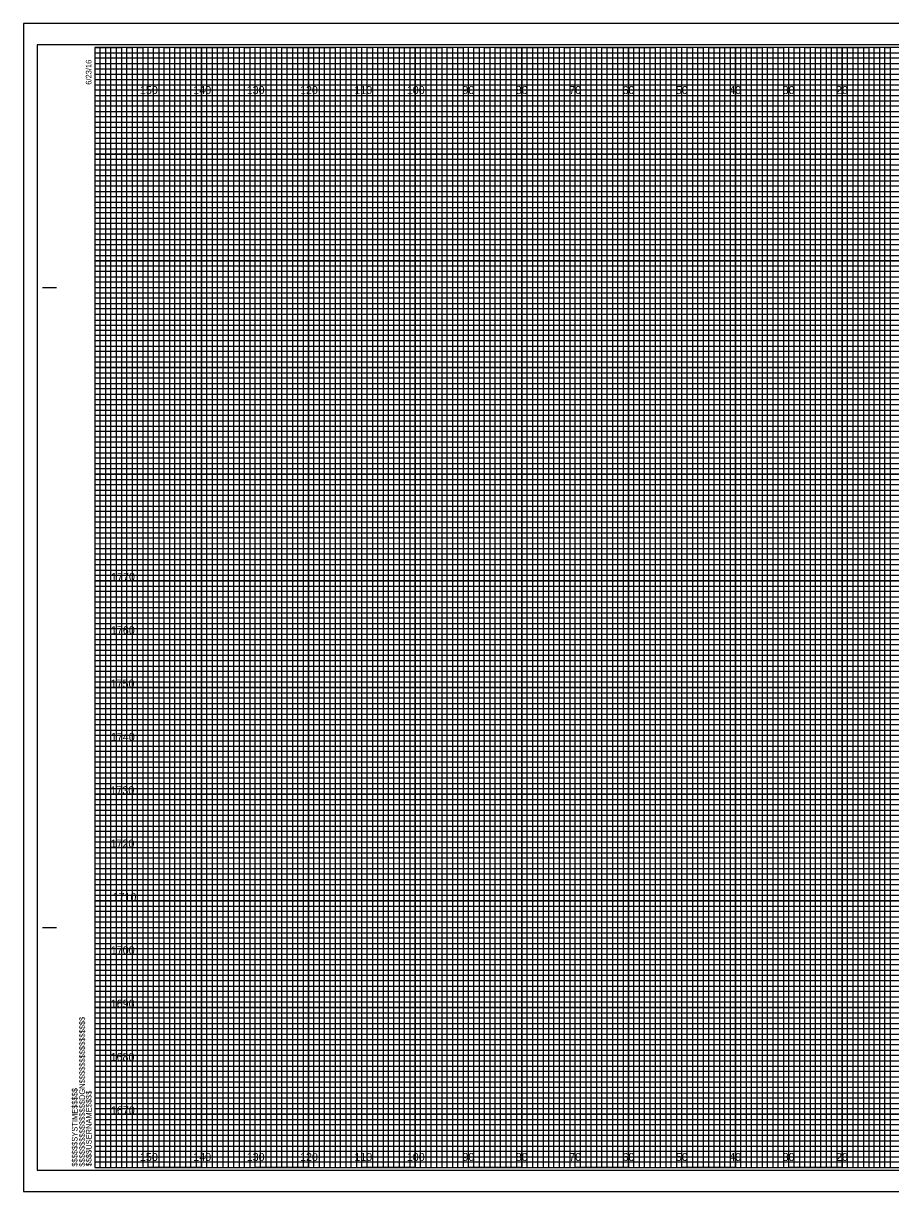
# Model space of a CAD drawing. Extents: x -419 to 4739, y -630 to 13534.
# Drawn here: x 1197.8 to 1360.3, y 199.6 to 418.6 of the extents above; entities that cross this region are included whole.
import ezdxf

# ---------------------------------------------------------------- set-up
doc = ezdxf.new("R2010")
doc.units = 0
for name, color, linetype in [('Old_Level_62', 7, 'Continuous'), ('Pattern 1', 7, 'Continuous'), ('Pattern 18', 7, 'Continuous'), ('Pattern 4', 7, 'Continuous'), ('Pattern 5', 7, 'Continuous'), ('Prop Dimension', 7, 'Continuous'), ('Prop Horizontal Alignment', 7, 'Continuous'), ('Raster_Level_0', 7, 'Continuous'), ('Scratch_Level_0', 7, 'Continuous'), ('Scratch_Level_3', 7, 'Continuous'), ('Scratch_Level_5', 7, 'Continuous')]:
    doc.layers.add(name, color=color, linetype=linetype)

msp = doc.modelspace()

# ---------------------------------------------------------------- linework, layer by layer
at = {"layer": 'Old_Level_62'}
for p, q in [((1201.42, 369.06), (1203.92, 369.06)), ((1201.52, 369.06), (1204.02, 369.06)), ((1201.42, 249.06), (1203.92, 249.06)), ((1201.52, 249.06), (1204.02, 249.06)), ((1211.22, 204.06), (1211.22, 204.06)), ((1211.22, 204.06), (1211.22, 204.06)), ((1211.22, 204.06), (1211.22, 204.06)), ((1211.22, 204.06), (1211.22, 204.06)), ((1211.22, 204.06), (1211.22, 204.06)), ((1211.22, 204.06), (1211.22, 204.06)), ((1211.22, 204.06), (1211.22, 204.06))]:
    msp.add_line(p, q, dxfattribs=at)
msp.add_lwpolyline([(1531.22, 414.06), (1211.22, 414.06), (1211.22, 204.06), (1531.22, 204.06)], close=True, dxfattribs=at)
at = {"layer": 'Pattern 18'}
msp.add_lwpolyline([(1197.82, 199.56), (1534.52, 199.56), (1534.52, 418.56), (1197.82, 418.56)], close=True, dxfattribs=at)
at = {"layer": 'Pattern 4'}
for p, q in [((1211.22, 413.06), (1471.22, 413.06)), ((1471.22, 412.04), (1211.22, 412.04)), ((1211.22, 412.04), (1211.22, 411.06)), ((1211.22, 411.06), (1471.22, 411.06)), ((1471.22, 409.95), (1211.22, 409.95)), ((1211.22, 409.95), (1211.22, 408.06)), ((1211.22, 408.06), (1531.22, 408.06))]:
    msp.add_line(p, q, dxfattribs=at)
for points in [[(1211.22, 407.06), (1481.22, 407.06), (1531.22, 407.06), (1531.22, 406.06), (1211.22, 406.06)], [(1211.22, 405.06), (1531.22, 405.06), (1531.22, 403.06), (1211.22, 403.06)], [(1211.22, 402.06), (1531.22, 402.06), (1531.22, 401.06), (1211.22, 401.04)], [(1211.22, 400.06), (1531.22, 400.06), (1531.22, 398.06), (1211.22, 398.06)], [(1211.22, 397.06), (1531.22, 397.06), (1531.22, 396.06), (1211.22, 396.06)], [(1211.22, 395.06), (1531.22, 395.06), (1531.22, 393.06), (1211.22, 393.06)], [(1211.22, 392.06), (1531.22, 392.06), (1531.22, 391.06), (1211.22, 391.06)], [(1211.22, 390.06), (1531.22, 390.06), (1531.22, 388.06), (1211.22, 388.06)], [(1211.22, 387.06), (1531.22, 387.06), (1531.22, 386.06), (1211.22, 386.06)], [(1211.22, 385.06), (1531.22, 385.06), (1531.22, 383.06), (1211.22, 383.06)], [(1211.22, 382.06), (1531.22, 382.06), (1531.22, 381.06), (1211.22, 381.06)], [(1211.22, 380.06), (1531.22, 380.06), (1531.22, 378.01), (1531.22, 377.06), (1531.22, 376.06), (1211.22, 376.06)], [(1211.22, 378.06), (1531.22, 378.06), (1531.22, 377.06), (1211.22, 377.06)], [(1211.22, 375.06), (1531.22, 375.06), (1531.22, 373.06), (1211.22, 373.09)], [(1211.22, 373.09), (1531.22, 373.06), (1531.22, 372.06), (1211.22, 372.06)], [(1211.22, 371.06), (1531.22, 371.06), (1531.22, 370.06), (1211.22, 370.06)], [(1211.22, 368.06), (1531.22, 368.06), (1531.22, 367.06), (1211.22, 367.06)], [(1211.22, 366.06), (1531.22, 366.06), (1531.22, 365.06), (1211.22, 365.06)], [(1211.15, 362.95), (1531.22, 362.95), (1531.22, 361.94), (1211.15, 361.94)], [(1211.22, 361.06), (1531.22, 361.06), (1531.22, 360.06), (1211.22, 360.06)], [(1211.22, 358.06), (1531.22, 358.06), (1531.22, 357.06), (1211.22, 357.06)], [(1211.22, 356.06), (1531.22, 356.06), (1531.22, 355.06), (1211.22, 355.06)], [(1211.22, 353.06), (1531.22, 353.06), (1531.22, 352.06), (1211.22, 352.06)], [(1211.22, 351.06), (1531.22, 351.06), (1531.22, 350.06), (1211.22, 350.06)], [(1211.22, 348.06), (1531.22, 348.06), (1531.22, 347.06), (1211.22, 347.06)], [(1211.22, 346.06), (1531.22, 346.06), (1531.22, 345.06), (1211.22, 345.06)], [(1211.22, 343.06), (1531.22, 343.06), (1531.21, 342.04), (1211.22, 342.06)], [(1211.22, 341.06), (1531.22, 341.06), (1531.22, 340.06), (1211.22, 340.06)], [(1211.22, 338.06), (1531.22, 338.06), (1531.22, 337.06), (1211.22, 337.06)], [(1211.22, 336.06), (1531.22, 336.06), (1531.22, 335.06), (1211.22, 335.06)], [(1211.22, 333.06), (1531.22, 333.06), (1531.22, 332.06), (1211.22, 332.06)], [(1211.22, 331.06), (1531.22, 331.06), (1531.22, 330.06), (1211.22, 330.06)], [(1211.22, 328.06), (1531.22, 328.06), (1531.22, 327.06), (1211.22, 327.06)], [(1211.22, 326.06), (1531.22, 326.06), (1531.22, 325.06), (1211.22, 325.06)], [(1211.22, 323.06), (1531.22, 323.06), (1531.22, 322.06), (1211.22, 322.06)], [(1211.22, 321.05), (1531.29, 320.97), (1531.22, 320.06), (1211.22, 320.06)], [(1211.22, 318.06), (1531.22, 318.06), (1531.22, 317.06), (1211.22, 317.06)], [(1211.22, 316.06), (1531.22, 316.06), (1531.22, 315.06), (1211.22, 315.06)], [(1211.22, 313.06), (1531.22, 313.06), (1531.22, 312.06), (1211.22, 312.06)], [(1211.22, 311.06), (1531.22, 311.06), (1531.22, 310.06), (1211.22, 310.06)], [(1211.22, 308.06), (1531.22, 308.06), (1531.22, 307.06), (1211.22, 307.06)], [(1211.22, 306.06), (1531.22, 306.06), (1531.22, 305.06), (1211.22, 305.06)], [(1211.22, 303.06), (1531.22, 303.06), (1531.22, 302.06), (1211.22, 302.06)], [(1211.22, 301.06), (1531.22, 301.06), (1531.22, 300.06), (1211.22, 300.06)], [(1211.22, 298.06), (1531.22, 298.06), (1531.22, 297.06), (1211.22, 297.06)], [(1211.22, 296.06), (1531.22, 296.06), (1531.22, 295.06), (1211.22, 295.06)], [(1211.22, 293.06), (1531.22, 293.06), (1531.22, 292.06), (1211.22, 292.06)], [(1211.22, 291.06), (1531.22, 291.06), (1531.22, 290.06), (1211.22, 290.06)], [(1211.22, 288.06), (1531.22, 288.06), (1531.22, 287.06), (1211.22, 287.06)], [(1211.22, 286.06), (1531.22, 286.06), (1531.22, 285.06), (1211.22, 285.06)], [(1211.22, 283.06), (1531.22, 283.06), (1531.21, 282.04), (1211.22, 282.06)], [(1211.22, 281.06), (1531.22, 281.06), (1531.22, 280.06), (1211.22, 280.06)], [(1211.22, 278.06), (1531.22, 278.06), (1531.22, 277.06), (1211.22, 277.06)], [(1211.22, 276.06), (1531.22, 276.06), (1531.22, 275.06), (1211.22, 275.06)], [(1211.22, 273.06), (1531.22, 273.06), (1531.22, 272.06), (1211.22, 272.06)], [(1211.22, 271.06), (1531.22, 271.06), (1531.22, 270.06), (1211.22, 270.06)], [(1211.22, 268.06), (1531.22, 268.06), (1531.22, 267.06), (1211.22, 267.06)], [(1211.22, 266.06), (1531.22, 266.06), (1531.22, 265.06), (1211.22, 265.06)], [(1211.22, 263.06), (1531.22, 263.06), (1531.22, 262.06), (1211.22, 262.06)], [(1211.22, 261.05), (1531.29, 260.97), (1531.22, 260.06), (1211.22, 260.06)], [(1211.22, 258.06), (1531.22, 258.06), (1531.22, 257.06), (1211.22, 257.06)], [(1211.22, 256.06), (1531.22, 256.06), (1531.22, 255.06), (1211.22, 255.06)], [(1211.22, 253.06), (1531.22, 253.06), (1531.22, 252.06), (1211.22, 252.06)], [(1211.22, 251.06), (1531.22, 251.06), (1531.22, 250.06), (1211.22, 250.06)], [(1211.22, 248.06), (1531.22, 248.06), (1531.22, 247.06), (1211.22, 247.06)], [(1211.22, 246.06), (1531.22, 246.06), (1531.22, 245.06), (1211.22, 245.06)], [(1211.22, 243.06), (1531.22, 243.06), (1531.22, 242.06), (1211.22, 242.06)], [(1211.22, 241.06), (1531.22, 241.06), (1531.22, 240.06), (1211.22, 240.06)], [(1211.22, 238.06), (1531.22, 238.06), (1531.22, 237.06), (1211.22, 237.06)], [(1211.22, 236.06), (1531.22, 236.06), (1531.22, 235.06), (1211.22, 235.06)], [(1211.22, 233.06), (1531.22, 233.06), (1531.22, 232.06), (1211.22, 232.06)], [(1211.22, 231.06), (1531.22, 231.06), (1531.22, 230.06), (1211.22, 230.06)], [(1211.22, 228.06), (1531.22, 228.06), (1531.22, 227.06), (1211.22, 227.06)], [(1211.22, 226.06), (1531.22, 226.06), (1531.22, 225.06), (1211.22, 225.06)], [(1211.22, 223.06), (1531.22, 223.06), (1531.22, 222.06), (1211.22, 222.06)], [(1211.22, 221.06), (1531.22, 221.06), (1531.22, 220.06), (1211.22, 220.06)], [(1211.22, 218.06), (1531.22, 218.06), (1531.22, 217.06), (1211.22, 217.06)], [(1211.22, 216.06), (1531.22, 216.06), (1531.22, 215.06), (1211.22, 215.06)], [(1211.22, 213.06), (1531.22, 213.06), (1531.22, 212.06), (1211.22, 212.06)], [(1211.22, 211.06), (1531.22, 211.06), (1531.22, 210.06), (1211.22, 210.06)], [(1211.22, 208.06), (1531.22, 208.06), (1531.22, 207.06), (1211.22, 207.06)], [(1211.22, 206.06), (1531.22, 206.06), (1531.22, 205.06), (1211.22, 205.06)]]:
    msp.add_lwpolyline(points, dxfattribs=at)
at = {"layer": 'Pattern 5'}
for p, q in [((1534.52, 418.56), (1197.82, 418.56)), ((1197.82, 418.56), (1197.82, 199.56)), ((1197.82, 199.56), (1534.52, 199.56))]:
    msp.add_line(p, q, dxfattribs=at)
at = {"layer": 'Prop Dimension'}
for points in [[(1211.22, 204.06), (1212.22, 204.06), (1212.22, 414.06), (1213.22, 414.06), (1213.22, 204.06)], [(1213.22, 204.06), (1214.22, 204.06), (1214.22, 414.06), (1215.22, 414.06), (1215.22, 204.06)], [(1216.22, 204.06), (1217.22, 204.06), (1217.22, 414.06), (1218.22, 414.06), (1218.22, 204.06)], [(1218.22, 204.06), (1219.22, 204.06), (1219.22, 414.06), (1220.22, 414.06), (1220.22, 204.06)], [(1221.22, 204.06), (1222.22, 204.06), (1222.22, 414.06), (1223.22, 414.06), (1223.22, 204.06)], [(1223.22, 204.06), (1224.22, 204.06), (1224.22, 414.06), (1225.22, 414.06), (1225.22, 204.06)], [(1226.22, 204.06), (1227.22, 204.06), (1227.22, 414.06), (1228.22, 414.06), (1228.22, 204.06)], [(1228.22, 204.06), (1229.22, 204.06), (1229.22, 414.06), (1230.22, 414.06), (1230.22, 204.06)], [(1231.22, 204.06), (1232.22, 204.06), (1232.22, 414.06), (1233.22, 414.06), (1233.22, 204.06)], [(1233.22, 204.06), (1234.22, 204.06), (1234.22, 414.06), (1235.22, 414.06), (1235.22, 204.06)], [(1236.22, 204.06), (1237.22, 204.06), (1237.22, 414.06), (1238.22, 414.06), (1238.22, 204.06)], [(1238.22, 204.06), (1239.22, 204.06), (1239.22, 414.06), (1240.22, 414.06), (1240.22, 204.06)], [(1241.22, 204.06), (1242.22, 204.06), (1242.22, 414.06), (1243.22, 414.06), (1243.22, 204.06)], [(1243.22, 204.06), (1244.22, 204.06), (1244.22, 414.06), (1245.22, 414.06), (1245.22, 204.06)], [(1246.22, 204.06), (1247.22, 204.06), (1247.22, 414.06), (1248.22, 414.06), (1248.22, 204.06)], [(1248.22, 204.06), (1249.22, 204.06), (1249.22, 414.06), (1250.22, 414.06), (1250.22, 204.06)], [(1251.22, 204.06), (1252.22, 204.06), (1252.22, 414.06), (1253.22, 414.06), (1253.22, 204.06)], [(1253.22, 204.06), (1254.22, 204.06), (1254.22, 414.06), (1255.22, 414.06), (1255.22, 204.06)], [(1256.22, 204.06), (1257.22, 204.06), (1257.22, 414.06), (1258.22, 414.06), (1258.22, 204.06)], [(1258.22, 204.06), (1259.22, 204.06), (1259.22, 414.06), (1260.22, 414.06), (1260.22, 204.06)], [(1261.22, 204.06), (1262.22, 204.06), (1262.22, 414.06), (1263.22, 414.06), (1263.22, 204.06)], [(1263.22, 204.06), (1264.22, 204.06), (1264.22, 414.06), (1265.22, 414.06), (1265.22, 204.06)], [(1266.22, 204.06), (1267.22, 204.06), (1267.22, 414.06), (1268.22, 414.06), (1268.22, 204.06)], [(1268.22, 204.06), (1269.22, 204.06), (1269.22, 414.06), (1270.22, 414.06), (1270.22, 204.06)], [(1271.22, 204.06), (1272.22, 204.06), (1272.22, 414.06), (1273.22, 414.06), (1273.22, 204.06)], [(1273.22, 204.06), (1274.22, 204.06), (1274.22, 414.06), (1275.22, 414.06), (1275.22, 204.06)], [(1276.22, 204.06), (1277.22, 204.06), (1277.22, 414.06), (1278.22, 414.06), (1278.22, 204.06)], [(1278.22, 204.06), (1279.22, 204.06), (1279.22, 414.06), (1280.22, 414.06), (1280.22, 204.06)], [(1281.22, 204.06), (1282.22, 204.06), (1282.22, 414.06), (1283.22, 414.06), (1283.22, 204.06)], [(1283.22, 204.06), (1284.22, 204.06), (1284.22, 414.06), (1285.22, 414.06), (1285.22, 204.06)], [(1286.22, 204.06), (1287.22, 204.06), (1287.22, 414.06), (1288.22, 414.06), (1288.22, 204.06)], [(1288.22, 204.06), (1289.22, 204.06), (1289.22, 414.06), (1290.22, 414.06), (1290.22, 204.06)], [(1291.22, 204.06), (1292.22, 204.06), (1292.22, 414.06), (1293.22, 414.06), (1293.22, 204.06)], [(1293.22, 204.06), (1294.22, 204.06), (1294.22, 414.06), (1295.22, 414.06), (1295.22, 204.06)], [(1296.22, 204.06), (1297.22, 204.06), (1297.22, 414.06), (1298.22, 414.06), (1298.22, 204.06)], [(1298.22, 204.06), (1299.22, 204.06), (1299.22, 414.06), (1300.22, 414.06), (1300.22, 204.06)], [(1301.22, 204.06), (1302.22, 204.06), (1302.22, 414.06), (1303.22, 414.06), (1303.22, 204.06)], [(1303.22, 204.06), (1304.22, 204.06), (1304.22, 414.06), (1305.22, 414.06), (1305.22, 204.06)], [(1306.22, 204.06), (1307.22, 204.06), (1307.22, 414.06), (1308.22, 414.06), (1308.22, 204.06)], [(1308.22, 204.06), (1309.22, 204.06), (1309.22, 414.06), (1310.22, 414.06), (1310.22, 204.06)], [(1311.22, 204.06), (1312.22, 204.06), (1312.22, 414.06), (1313.22, 414.06), (1313.22, 204.06)], [(1313.22, 204.06), (1314.22, 204.06), (1314.22, 414.06), (1315.22, 414.06), (1315.22, 204.06)], [(1316.22, 204.06), (1317.22, 204.06), (1317.22, 414.06), (1318.22, 414.06), (1318.22, 204.06)], [(1318.22, 204.06), (1319.22, 204.06), (1319.22, 414.06), (1320.22, 414.06), (1320.22, 204.06)], [(1321.22, 204.06), (1322.22, 204.06), (1322.22, 414.06), (1323.22, 414.06), (1323.22, 204.06)], [(1323.22, 204.06), (1324.22, 204.06), (1324.22, 414.06), (1325.22, 414.06), (1325.22, 204.06)], [(1326.22, 204.06), (1327.22, 204.06), (1327.22, 414.06), (1328.22, 414.06), (1328.22, 204.06)], [(1328.22, 204.06), (1329.22, 204.06), (1329.22, 414.06), (1330.22, 414.06), (1330.22, 204.06)], [(1331.22, 204.06), (1332.22, 204.06), (1332.22, 414.06), (1333.22, 414.06), (1333.22, 204.06)], [(1333.22, 204.06), (1334.22, 204.06), (1334.22, 414.06), (1335.22, 414.06), (1335.22, 204.06)], [(1336.22, 204.06), (1337.22, 204.06), (1337.22, 414.06), (1338.22, 414.06), (1338.22, 204.06)], [(1338.22, 204.06), (1339.22, 204.06), (1339.22, 414.06), (1340.22, 414.06), (1340.22, 204.06)], [(1341.22, 204.06), (1342.22, 204.06), (1342.22, 414.06), (1343.22, 414.06), (1343.22, 204.06)], [(1343.22, 204.06), (1344.22, 204.06), (1344.22, 414.06), (1345.22, 414.06), (1345.22, 204.06)], [(1346.22, 204.06), (1347.22, 204.06), (1347.22, 414.06), (1348.22, 414.06), (1348.22, 204.06)], [(1348.22, 204.06), (1349.22, 204.06), (1349.22, 414.06), (1350.22, 414.06), (1350.22, 204.06)], [(1351.22, 204.06), (1352.22, 204.06), (1352.22, 414.06), (1353.22, 414.06), (1353.22, 204.06)], [(1353.22, 204.06), (1354.22, 204.06), (1354.22, 414.06), (1355.22, 414.06), (1355.22, 204.06)], [(1356.22, 204.06), (1357.22, 204.06), (1357.22, 414.06), (1358.22, 414.06), (1358.22, 204.06)], [(1358.22, 204.06), (1359.22, 204.06), (1359.22, 414.06), (1360.22, 414.06), (1360.22, 204.06)]]:
    msp.add_lwpolyline(points, dxfattribs=at)
at = {"layer": 'Prop Horizontal Alignment'}
for points in [[(1211.22, 414.06), (1216.22, 414.06), (1216.22, 204.06), (1226.22, 204.06), (1226.22, 414.06), (1236.22, 414.06), (1236.22, 204.06), (1246.22, 204.06), (1246.22, 414.06), (1256.22, 414.06), (1256.22, 204.06), (1266.22, 204.06), (1266.22, 414.06), (1276.22, 414.06), (1276.22, 204.06), (1286.22, 204.06), (1286.22, 414.06), (1296.22, 414.06), (1296.22, 204.06), (1306.22, 204.06), (1306.22, 414.06), (1316.22, 414.06), (1316.22, 204.06), (1326.22, 204.06), (1326.22, 414.06), (1336.22, 414.06), (1336.22, 204.06), (1346.22, 204.06), (1346.22, 414.06), (1356.22, 414.06), (1356.22, 204.06), (1366.22, 204.06)], [(1211.22, 409.06), (1486.22, 409.06)], [(1211.22, 389.06), (1531.22, 389.06), (1531.22, 399.06), (1211.22, 399.06)], [(1211.22, 369.06), (1531.22, 369.06), (1531.22, 379.06), (1211.22, 379.06)], [(1211.22, 349.06), (1531.22, 349.06), (1531.22, 359.06), (1211.22, 359.06)], [(1211.22, 329.06), (1531.22, 329.06), (1531.22, 339.06), (1211.22, 339.06)], [(1211.22, 309.06), (1531.22, 309.06), (1531.22, 319.06), (1211.22, 319.06)], [(1211.22, 289.06), (1531.22, 289.06), (1531.22, 299.06), (1211.22, 299.06)], [(1211.22, 269.06), (1531.22, 269.06), (1531.22, 279.06), (1211.22, 279.06)], [(1211.22, 249.06), (1531.22, 249.06), (1531.22, 259.06), (1211.22, 259.06)], [(1211.22, 229.06), (1531.22, 229.06), (1531.22, 239.06), (1211.22, 239.06)], [(1211.22, 209.06), (1531.22, 209.06), (1531.22, 219.06), (1211.22, 219.06)]]:
    msp.add_lwpolyline(points, dxfattribs=at)
at = {"layer": 'Scratch_Level_0'}
for p, q in [((1221.22, 204.06), (1221.22, 414.06)), ((1231.22, 204.06), (1231.22, 414.06)), ((1241.22, 204.06), (1241.22, 414.06)), ((1251.22, 204.06), (1251.22, 414.06)), ((1261.22, 204.06), (1261.22, 414.06)), ((1271.22, 204.06), (1271.22, 414.06)), ((1281.22, 204.06), (1281.22, 414.06)), ((1291.22, 204.06), (1291.22, 414.06)), ((1301.22, 204.06), (1301.22, 414.06)), ((1311.22, 204.06), (1311.22, 414.06)), ((1321.22, 204.06), (1321.22, 414.06)), ((1331.22, 204.06), (1331.22, 414.06)), ((1341.22, 204.06), (1341.22, 414.06)), ((1351.22, 204.06), (1351.22, 414.06)), ((1211.22, 404.06), (1531.22, 404.06)), ((1211.22, 394.06), (1531.22, 394.06)), ((1211.22, 384.06), (1531.22, 384.06)), ((1211.22, 374.06), (1531.22, 374.06)), ((1211.22, 364.06), (1531.22, 364.06)), ((1211.22, 354.06), (1531.22, 354.06)), ((1211.22, 344.06), (1531.22, 344.06)), ((1211.22, 334.06), (1531.22, 334.06)), ((1211.22, 324.06), (1531.22, 324.06)), ((1211.22, 314.06), (1531.22, 314.06)), ((1211.22, 304.06), (1531.22, 304.06)), ((1211.22, 294.06), (1531.22, 294.06)), ((1211.22, 284.06), (1531.22, 284.06)), ((1211.22, 274.06), (1531.22, 274.06)), ((1211.22, 264.06), (1531.22, 264.06)), ((1211.22, 254.06), (1531.22, 254.06)), ((1211.22, 244.06), (1531.22, 244.06)), ((1211.22, 234.06), (1531.22, 234.06)), ((1211.22, 224.06), (1531.22, 224.06)), ((1211.22, 214.06), (1531.22, 214.06))]:
    msp.add_line(p, q, dxfattribs=at)
at = {"layer": 'Scratch_Level_3'}
for p, q in [((1221.22, 414.06), (1211.22, 414.06)), ((1221.22, 204.06), (1221.22, 414.06)), ((1241.22, 414.06), (1231.22, 414.06)), ((1231.22, 414.06), (1231.22, 204.06)), ((1241.22, 204.06), (1241.22, 414.06)), ((1261.22, 414.06), (1251.22, 414.06)), ((1251.22, 414.06), (1251.22, 204.06)), ((1261.22, 204.06), (1261.22, 414.06)), ((1281.22, 414.06), (1271.22, 414.06)), ((1271.22, 414.06), (1271.22, 204.06)), ((1281.22, 204.06), (1281.22, 414.06)), ((1301.22, 414.06), (1291.22, 414.06)), ((1291.22, 414.06), (1291.22, 204.06)), ((1301.22, 204.06), (1301.22, 414.06)), ((1321.22, 414.06), (1311.22, 414.06)), ((1311.22, 414.06), (1311.22, 204.06)), ((1321.22, 204.06), (1321.22, 414.06)), ((1341.22, 414.06), (1331.22, 414.06)), ((1331.22, 414.06), (1331.22, 204.06)), ((1341.22, 204.06), (1341.22, 414.06)), ((1361.22, 414.06), (1351.22, 414.06)), ((1351.22, 414.06), (1351.22, 204.06)), ((1231.22, 204.06), (1221.22, 204.06)), ((1251.22, 204.06), (1241.22, 204.06)), ((1271.22, 204.06), (1261.22, 204.06)), ((1291.22, 204.06), (1281.22, 204.06)), ((1311.22, 204.06), (1301.22, 204.06)), ((1331.22, 204.06), (1321.22, 204.06)), ((1351.22, 204.06), (1341.22, 204.06))]:
    msp.add_line(p, q, dxfattribs=at)
for points in [[(1211.22, 404.06), (1531.22, 404.06), (1531.22, 394.06), (1211.22, 394.06)], [(1211.22, 384.06), (1531.22, 384.06), (1531.22, 374.06), (1211.22, 374.06)], [(1211.22, 364.06), (1531.22, 364.06), (1531.22, 354.06), (1211.22, 354.06)], [(1211.22, 344.06), (1531.22, 344.06), (1531.22, 334.06), (1211.22, 334.06)], [(1211.22, 324.06), (1531.22, 324.06), (1531.22, 314.06), (1211.22, 314.06)], [(1211.22, 304.06), (1531.22, 304.06), (1531.22, 294.06), (1211.22, 294.06)], [(1211.22, 284.06), (1531.22, 284.06), (1531.22, 274.06), (1211.22, 274.06)], [(1211.22, 264.06), (1531.22, 264.06), (1531.22, 254.06), (1211.22, 254.06)], [(1211.22, 244.06), (1531.22, 244.06), (1531.22, 234.06), (1211.22, 234.06)], [(1211.22, 224.06), (1531.22, 224.06), (1531.22, 214.06), (1211.22, 214.06)]]:
    msp.add_lwpolyline(points, dxfattribs=at)
at = {"layer": 'Scratch_Level_5'}
msp.add_lwpolyline([(1200.42, 203.56), (1533.62, 203.56), (1533.62, 414.56), (1200.42, 414.56)], close=True, dxfattribs=at)

# ---------------------------------------------------------------- texts
at = {"layer": 'Old_Level_62'}
for s, p in [('6/23/16', (1210.57, 407.06)), ('$$$$$$$$$$$$$$$$DGN$$$$$$$$$$$$$$$$', (1209.34, 204.24)), ('$$$$$$SYSTIME$$$$$', (1207.96, 204.24)), ('$$$$USERNAME$$$$', (1210.6, 204.29))]:
    msp.add_text(s, height=1.05, rotation=90, dxfattribs=at).set_placement(p)
at = {"layer": 'Pattern 1'}
for s, p in [('1770', (1214.26, 314.06)), ('1760', (1214.22, 304.06)), ('1750', (1214.17, 294.06)), ('1740', (1214.22, 284.06)), ('1730', (1214.14, 274.06)), ('1720', (1214.15, 264.06)), ('1710', (1214.53, 254.06)), ('1700', (1214.2, 244.06)), ('1690', (1214.19, 234.06)), ('1680', (1214.16, 224.06)), ('1670', (1214.22, 214.06))]:
    msp.add_text(s, height=1.5, dxfattribs=at).set_placement(p)
at = {"layer": 'Raster_Level_0'}
for s, p in [('150', (1219.66, 405.31)), ('140', (1229.66, 405.31)), ('130', (1239.66, 405.31)), ('120', (1249.66, 405.31)), ('110', (1259.84, 405.31)), ('100', (1269.66, 405.31)), ('90', (1280.08, 405.31)), ('80', (1290.08, 405.31)), ('70', (1300.08, 405.31)), ('60', (1310.08, 405.31)), ('50', (1320.08, 405.31)), ('40', (1330.08, 405.31)), ('30', (1340.08, 405.31)), ('20', (1350.08, 405.31)), ('150', (1219.66, 205.31)), ('140', (1229.66, 205.31)), ('130', (1239.66, 205.31)), ('120', (1249.66, 205.31)), ('110', (1259.84, 205.31)), ('100', (1269.66, 205.31)), ('90', (1280.08, 205.31)), ('80', (1290.08, 205.31)), ('70', (1300.08, 205.31)), ('60', (1310.08, 205.31)), ('50', (1320.08, 205.31)), ('40', (1330.08, 205.31)), ('30', (1340.08, 205.31)), ('20', (1350.08, 205.31))]:
    msp.add_text(s, height=1.5, dxfattribs=at).set_placement(p)

doc.saveas('drawing.dxf')
